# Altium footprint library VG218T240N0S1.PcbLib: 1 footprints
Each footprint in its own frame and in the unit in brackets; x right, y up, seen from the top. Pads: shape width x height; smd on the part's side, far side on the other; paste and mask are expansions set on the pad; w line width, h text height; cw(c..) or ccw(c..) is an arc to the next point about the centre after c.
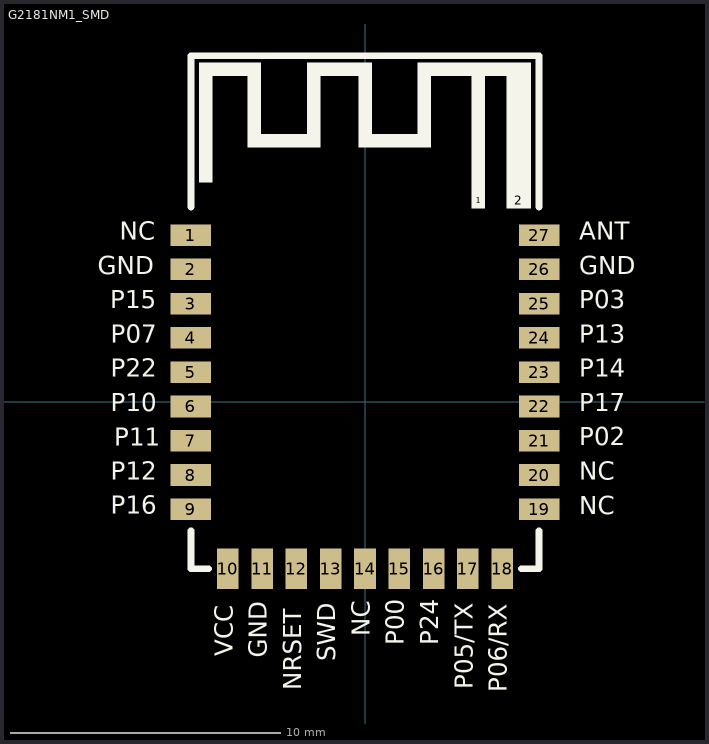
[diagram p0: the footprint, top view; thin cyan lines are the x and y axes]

## G2181NM1_SMD [mm]
pads (29):
  rect 1.5x0.8 smd: 1(-6.45,6.18) 2(-6.45,4.91) 3(-6.45,3.64) 4(-6.45,2.37) 5(-6.45,1.1) 6(-6.45,-0.17) 7(-6.45,-1.44) 8(-6.45,-2.71) 9(-6.45,-3.98) 19(6.45,-3.98) 20(6.45,-2.71) 21(6.45,-1.44) 22(6.45,-0.17) 23(6.45,1.1) 24(6.45,2.37) 25(6.45,3.64) 26(6.45,4.91) 27(6.45,6.18)
  rect 0.4x0.6 on Top Overlay paste+0 mask+0.064: 1(4.21,7.471)
  rect 0.8x0.6 on Top Overlay paste+0 mask+0.064: 2(5.693,7.471)
  rect 0.8x1.5 smd: 10(-5.08,-6.18) 11(-3.81,-6.18) 12(-2.54,-6.18) 13(-1.27,-6.18) 14(0,-6.18) 15(1.27,-6.18) 16(2.54,-6.18) 17(3.81,-6.18) 18(5.08,-6.18)
Top Overlay:
  region: -3.85,12.566 -6.15,12.566 -6.15,12.066 -3.85,12.066
  region: -1.65,12.246 -2.15,12.246 -2.15,9.426 -1.65,9.426
  region: 0.25,12.246 -0.25,12.246 -0.25,9.426 0.25,9.426
  region: 2.36,9.921 -0.18,9.921 -0.18,9.426 2.36,9.426
  region: 4.45,12.297 3.95,12.297 3.95,7.166 4.45,7.166
  region: -1.665,9.926 -4.154,9.926 -4.154,9.426 -1.665,9.426
  region: 6.15,12.566 1.95,12.566 1.95,12.066 6.15,12.066
  region: -3.85,12.246 -4.35,12.246 -4.35,9.426 -3.85,9.426
  region: 0.25,12.566 -2.15,12.566 -2.15,12.066 0.25,12.066
  region: 2.45,12.246 1.95,12.246 1.95,9.426 2.45,9.426
  region: -5.65,12.246 -6.15,12.246 -6.15,8.126 -5.65,8.126
  region: 6.15,12.271 5.25,12.271 5.25,7.166 6.15,7.166
  lines w0.254: -6.45,-4.774 -6.45,-6.18 -5.791,-6.18 ; -6.45,7.214 -6.45,12.82 6.45,12.82 6.45,7.214 ; 5.791,-6.18 6.45,-6.18 6.45,-4.774
  text "ANT" at 7.936,5.781 h1.14
  text "GND" at 7.936,4.511 h1.14
  text "P03" at 7.936,3.246 h1.14
  text "P13" at 7.936,1.976 h1.14
  text "P14" at 7.936,0.7 h1.14
  text "P17" at 7.936,-0.57 h1.14
  text "P02" at 7.936,-1.834 h1.14
  text "NC" at 7.936,-3.109 h1.14
  text "NC" at 7.936,-4.379 h1.14
  text "NC" at -9.09,5.781 h1.14
  text "P12" at -9.418,-3.11 h1.14
  text "P11" at -9.284,-1.84 h1.14
  text "P22" at -9.418,0.7 h1.14
  text "P15" at -9.431,3.246 h1.14
  text "GND" at -9.895,4.511 h1.14
  text "P16" at -9.426,-4.374 h1.14
  text "P10" at -9.423,-0.564 h1.14
  text "P07" at -9.426,1.976 h1.14
  text "VCC" at -4.681,-9.431 h1.14
  text "GND" at -3.411,-9.481 h1.14
  text "NRSET" at -2.141,-10.683 h1.14
  text "SWD" at -0.871,-9.603 h1.14
  text "NC" at 0.399,-8.676 h1.14
  text "P00" at 1.664,-9.01 h1.14
  text "P24" at 2.941,-9.009 h1.14
  text "P05/TX" at 4.209,-10.641 h1.14
  text "P06/RX" at 5.479,-10.754 h1.14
